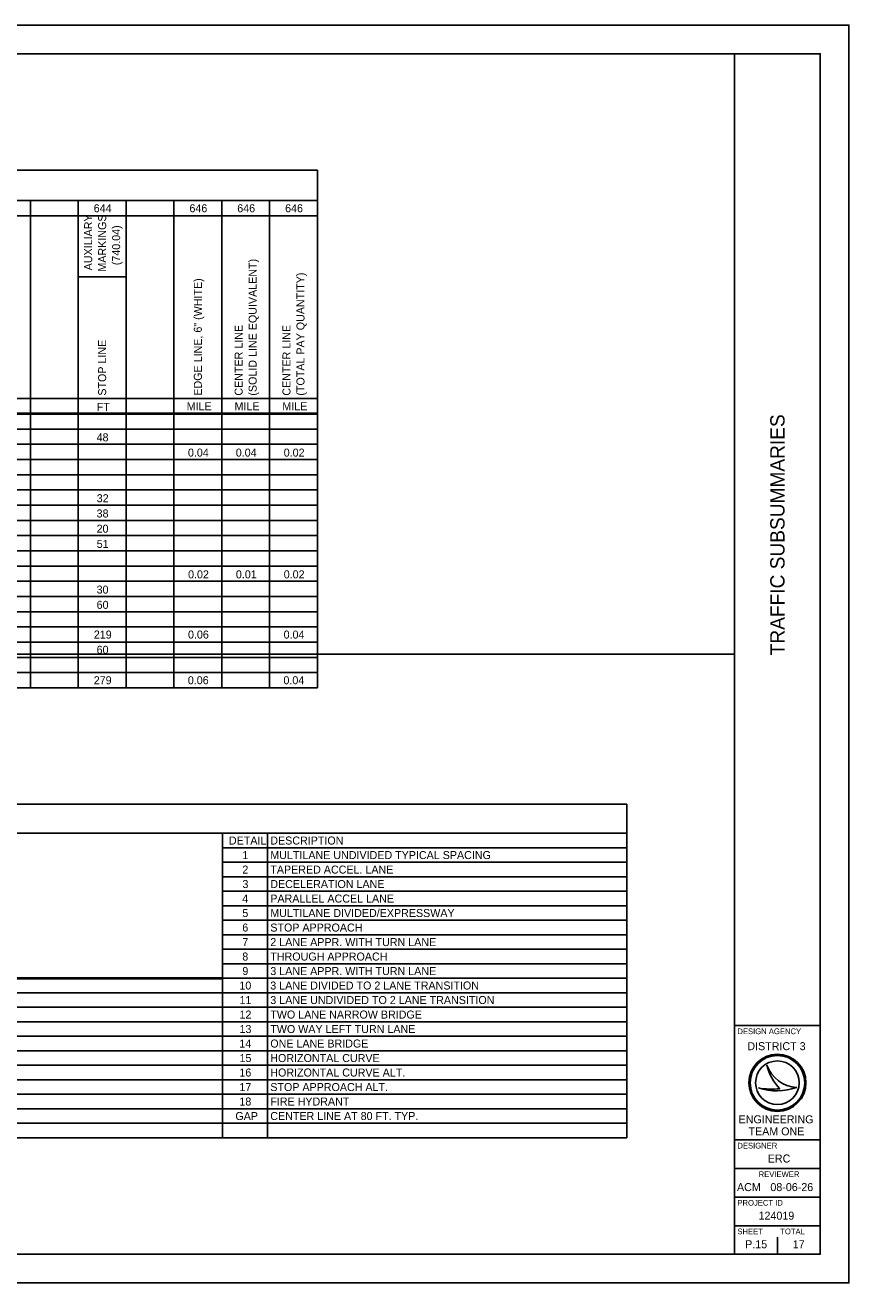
# Model space of a CAD drawing. Extents: x 0 to 34, y 0 to 22.
# Drawn here: x 19.59 to 34, y 0 to 22 of the extents above; entities that cross this region are included whole.
import ezdxf

# ---------------------------------------------------------------- set-up
doc = ezdxf.new("R2010")
doc.units = 0
for name, color, linetype in [('SC_Scratch1', 7, 'Continuous'), ('SH_Border', 7, 'Continuous'), ('SH_Cut_Line', 7, 'Continuous'), ('SH_Data', 7, 'Continuous')]:
    doc.layers.add(name, color=color, linetype=linetype)

msp = doc.modelspace()

# ---------------------------------------------------------------- linework, layer by layer
at = {"layer": 'SC_Scratch1'}
for p, q in [((1.5, 21.5), (32, 21.5)), ((1.5, 11), (32, 11))]:
    msp.add_line(p, q, dxfattribs=at)
at = {"layer": 'SH_Border'}
for p, q in [((32, 0.5), (32, 21.5)), ((32, 4.5), (33.5, 4.5)), ((32, 2.5), (33.5, 2.5)), ((32, 2), (33.5, 2)), ((32, 1.5), (33.5, 1.5)), ((32, 1), (33.5, 1))]:
    msp.add_line(p, q, dxfattribs=at)
msp.add_lwpolyline([(1.5, 21.5), (33.5, 21.5), (33.5, 0.5), (1.5, 0.5)], close=True, dxfattribs=at)
at = {"layer": 'SH_Cut_Line'}
msp.add_lwpolyline([(0, 0), (34, 0), (34, 22), (0, 22)], close=True, dxfattribs=at)
at = {"layer": 'SH_Data'}
for p, q in [((8.799, 19.463), (24.701, 19.463)), ((24.701, 19.463), (24.701, 15.193)), ((8.799, 18.93), (24.701, 18.93)), ((19.679, 18.93), (19.679, 15.21)), ((20.516, 18.93), (20.516, 15.21)), ((21.353, 18.93), (21.353, 15.21)), ((22.19, 18.93), (22.19, 15.21)), ((23.027, 18.93), (23.027, 15.21)), ((23.864, 18.93), (23.864, 15.21)), ((13.821, 18.664), (24.701, 18.664)), ((20.516, 17.598), (21.353, 17.598)), ((11.31, 15.468), (24.701, 15.468)), ((8.799, 15.21), (24.701, 15.21)), ((8.799, 15.193), (24.701, 15.193)), ((19.679, 15.193), (19.679, 10.408)), ((20.516, 15.193), (20.516, 10.408)), ((21.353, 15.193), (21.353, 10.408)), ((22.19, 15.193), (22.19, 10.408)), ((23.027, 15.193), (23.027, 10.408)), ((23.864, 15.193), (23.864, 10.408)), ((24.701, 15.21), (24.701, 10.408)), ((8.799, 14.935), (24.701, 14.935)), ((8.799, 14.669), (24.701, 14.669)), ((8.799, 14.403), (24.701, 14.403)), ((8.799, 14.136), (24.701, 14.136)), ((8.799, 13.87), (24.701, 13.87)), ((8.799, 13.604), (24.701, 13.604)), ((8.799, 13.338), (24.701, 13.338)), ((8.799, 13.071), (24.701, 13.071)), ((8.799, 12.805), (24.701, 12.805)), ((8.799, 12.539), (24.701, 12.539)), ((8.799, 12.272), (24.701, 12.272)), ((8.799, 12.006), (24.701, 12.006)), ((8.799, 11.74), (24.701, 11.74)), ((8.799, 11.473), (24.701, 11.473)), ((8.799, 11.207), (24.701, 11.207)), ((8.799, 10.941), (24.701, 10.941)), ((8.799, 10.674), (24.701, 10.674)), ((8.799, 10.408), (24.701, 10.408)), ((3.384, 8.371), (30.116, 8.371)), ((30.116, 8.371), (30.116, 2.537)), ((3.384, 7.864), (30.116, 7.864)), ((23.04, 7.864), (23.04, 2.537)), ((23.826, 7.864), (23.826, 2.537)), ((23.04, 7.61), (30.116, 7.61)), ((23.04, 7.356), (30.116, 7.356)), ((23.04, 7.103), (30.116, 7.103)), ((23.04, 6.849), (30.116, 6.849)), ((23.04, 6.595), (30.116, 6.595)), ((23.04, 6.342), (30.116, 6.342)), ((23.04, 6.088), (30.116, 6.088)), ((23.04, 5.835), (30.116, 5.835)), ((23.04, 5.581), (30.116, 5.581)), ((3.384, 5.336), (23.04, 5.336)), ((3.384, 5.319), (23.04, 5.319)), ((23.04, 5.327), (30.116, 5.327)), ((3.384, 5.074), (30.116, 5.074)), ((3.384, 4.82), (30.116, 4.82)), ((3.384, 4.566), (30.116, 4.566)), ((3.384, 4.313), (30.116, 4.313)), ((3.384, 4.059), (30.116, 4.059)), ((3.384, 3.806), (30.116, 3.806)), ((32.567, 3.81), (32.567, 3.81)), ((3.384, 3.552), (30.116, 3.552)), ((32.417, 3.41), (32.417, 3.41)), ((32.75, 3.5), (32.75, 3.5)), ((33.087, 3.419), (33.087, 3.419)), ((3.384, 3.298), (30.116, 3.298)), ((3.384, 3.045), (30.116, 3.045)), ((13.605, 2.791), (30.116, 2.791)), ((3.384, 2.537), (30.116, 2.537)), ((32.375, 0.675), (32.375, 0.675)), ((32.75, 0.5), (32.75, 0.8))]:
    msp.add_line(p, q, dxfattribs=at)
for radius in [0.5, 0.477, 0.477, 0.382]:
    msp.add_circle((32.75, 3.5), radius, dxfattribs=at)
for centre, radius, start, end in [((33.116, 3.998), 0.58, 198.9257, 198.9319), ((33.347, 3.97), 0.796, 191.6379, 191.6421), ((33.116, 3.998), 0.58, 198.9319, 267.1657), ((33.347, 3.97), 0.796, 191.6421, 226.0947), ((32.739, 4.37), 1.013, 251.4576, 290.0832), ((32.648, 4.654), 1.266, 259.4964, 259.4995), ((32.739, 4.37), 1.013, 251.4527, 251.4576), ((32.648, 4.654), 1.266, 259.4995, 276.6672)]:
    msp.add_arc(centre, radius, start, end, dxfattribs=at)

# ---------------------------------------------------------------- texts
for s, height, p in [('644', 0.14, (20.787, 18.727)), ('646', 0.14, (22.462, 18.727)), ('646', 0.14, (23.299, 18.727)), ('646', 0.14, (24.136, 18.727)), ('MILE', 0.14, (22.414, 15.265)), ('MILE', 0.14, (23.251, 15.265)), ('MILE', 0.14, (24.088, 15.265)), ('FT', 0.14, (20.842, 15.252)), ('48', 0.14, (20.838, 14.72)), ('0.04', 0.14, (22.436, 14.453)), ('0.04', 0.14, (23.273, 14.453)), ('0.02', 0.14, (24.112, 14.453)), ('32', 0.14, (20.84, 13.655)), ('38', 0.14, (20.838, 13.388)), ('20', 0.14, (20.838, 13.122)), ('51', 0.14, (20.84, 12.856)), ('0.02', 0.14, (22.438, 12.323)), ('0.01', 0.14, (23.275, 12.323)), ('0.02', 0.14, (24.112, 12.323)), ('30', 0.14, (20.838, 12.057)), ('60', 0.14, (20.838, 11.79)), ('219', 0.14, (20.789, 11.27)), ('0.06', 0.14, (22.437, 11.27)), ('0.04', 0.14, (24.11, 11.27)), ('60', 0.14, (20.838, 11.004)), ('279', 0.14, (20.788, 10.471)), ('0.06', 0.14, (22.434, 10.471)), ('0.04', 0.14, (24.107, 10.471)), ('DETAIL', 0.14, (23.153, 7.667)), ('DESCRIPTION', 0.14, (23.877, 7.667)), ('1', 0.14, (23.388, 7.413)), ('MULTILANE UNDIVIDED TYPICAL SPACING', 0.14, (23.877, 7.413)), ('2', 0.14, (23.388, 7.159)), ('TAPERED ACCEL. LANE', 0.14, (23.877, 7.159)), ('3', 0.14, (23.389, 6.906)), ('DECELERATION LANE', 0.14, (23.877, 6.906)), ('4', 0.14, (23.386, 6.652)), ('PARALLEL ACCEL LANE', 0.14, (23.877, 6.652)), ('5', 0.14, (23.388, 6.399)), ('MULTILANE DIVIDED/EXPRESSWAY', 0.14, (23.877, 6.399)), ('6', 0.14, (23.387, 6.145)), ('STOP APPROACH', 0.14, (23.877, 6.145)), ('7', 0.14, (23.387, 5.891)), ('2 LANE APPR. WITH TURN LANE', 0.14, (23.877, 5.891)), ('8', 0.14, (23.387, 5.638)), ('THROUGH APPROACH', 0.14, (23.877, 5.638)), ('9', 0.14, (23.388, 5.384)), ('3 LANE APPR. WITH TURN LANE', 0.14, (23.877, 5.384)), ('10', 0.14, (23.336, 5.131)), ('3 LANE DIVIDED TO 2 LANE TRANSITION', 0.14, (23.877, 5.131)), ('11', 0.14, (23.338, 4.877)), ('3 LANE UNDIVIDED TO 2 LANE TRANSITION', 0.14, (23.877, 4.877)), ('12', 0.14, (23.338, 4.623)), ('TWO LANE NARROW BRIDGE', 0.14, (23.877, 4.623)), ('13', 0.14, (23.338, 4.37)), ('TWO WAY LEFT TURN LANE', 0.14, (23.877, 4.37)), ('DESIGN AGENCY', 0.1, (32.05, 4.35)), ('14', 0.14, (23.335, 4.116)), ('ONE LANE BRIDGE', 0.14, (23.877, 4.116)), ('DISTRICT 3', 0.14, (32.224, 4.07)), ('15', 0.14, (23.338, 3.862)), ('HORIZONTAL CURVE', 0.14, (23.877, 3.862)), ('16', 0.14, (23.336, 3.609)), ('HORIZONTAL CURVE ALT.', 0.14, (23.877, 3.609)), ('17', 0.14, (23.337, 3.355)), ('STOP APPROACH ALT.', 0.14, (23.877, 3.355)), ('18', 0.14, (23.336, 3.102)), ('FIRE HYDRANT', 0.14, (23.877, 3.102)), ('GAP', 0.14, (23.266, 2.848)), ('CENTER LINE AT 80 FT. TYP.', 0.14, (23.877, 2.848)), ('ENGINEERING', 0.14, (32.071, 2.79)), ('TEAM ONE', 0.14, (32.244, 2.58)), ('DESIGNER', 0.1, (32.05, 2.35)), ('ERC', 0.14, (32.581, 2.105)), ('REVIEWER', 0.1, (32.422, 1.85)), ('ACM', 0.14, (32.043, 1.605)), ('08-06-26', 0.14, (32.627, 1.605)), ('PROJECT ID', 0.1, (32.05, 1.35)), ('124019', 0.14, (32.42, 1.105)), ('SHEET', 0.1, (32.05, 0.85)), ('TOTAL', 0.1, (32.8, 0.85)), ('P.15', 0.14, (32.185, 0.605)), ('17', 0.14, (33.018, 0.605))]:
    msp.add_text(s, height=height, dxfattribs=at).set_placement(p)
for s, height, p in [('AUXILIARY ', 0.14, (20.76, 17.711)), ('MARKINGS ', 0.14, (21.005, 17.689)), ('(740.04)', 0.14, (21.25, 17.801)), ('(SOLID LINE EQUIVALENT)', 0.14, (23.638, 15.519)), ('(TOTAL PAY QUANTITY)', 0.14, (24.475, 15.519)), ('EDGE LINE, 6" (WHITE)', 0.14, (22.679, 15.519)), ('CENTER LINE', 0.14, (23.393, 15.519)), ('CENTER LINE', 0.14, (24.23, 15.519)), ('STOP LINE', 0.14, (21.005, 15.519)), ('TRAFFIC SUBSUMMARIES', 0.25, (32.875, 10.977))]:
    msp.add_text(s, height=height, rotation=90, dxfattribs=at).set_placement(p)

doc.saveas('drawing.dxf')
